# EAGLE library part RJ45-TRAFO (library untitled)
RJ45 socket with integrated magnetics Naming: AmphenolLMJ1598824110DT39 TMERJ45-TRAFO Author: Petr Kalandra Datasheet: http://zefiryn.tme.pl/dok/zlacza/rjtrafo.pdf
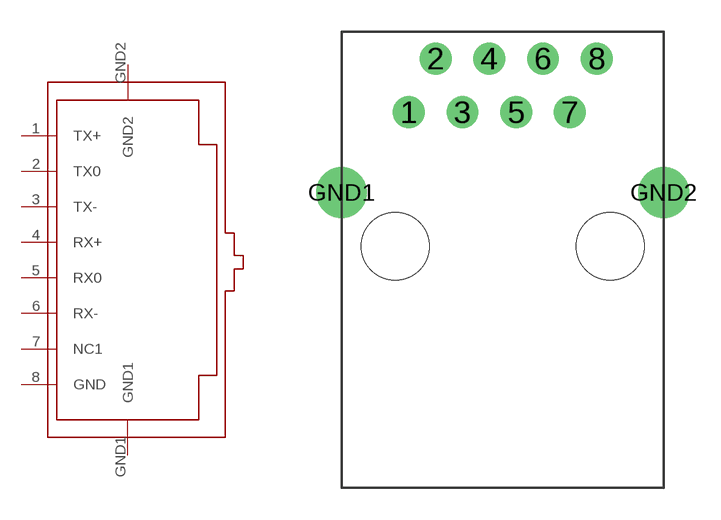
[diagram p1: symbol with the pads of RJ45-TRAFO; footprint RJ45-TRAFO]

Designator prefix -

## RJ45-TRAFO  [RJ45-TRAFO]
1  TX+
2  TX0
3  TX-
4  RX+
5  RX0
6  RX-
7  NC1  nc
8  GND  sup
GND1  GND1  sup
GND2  GND2  sup

## Footprint RJ45-TRAFO (pad centres in mm)
RJ45 without LED pins
drill 1 round: 1 -4.445,6.35; 2 -3.175,8.89; 3 -1.905,6.35; 4 -0.635,8.89; 5 0.635,6.35; 6 1.905,8.89; 7 3.175,6.35; 8 4.445,8.89
drill 1.6 round: GND1 -7.62,2.54; GND2 7.62,2.54
hole 3.2 at -5.08,0
hole 3.2 at 5.08,0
